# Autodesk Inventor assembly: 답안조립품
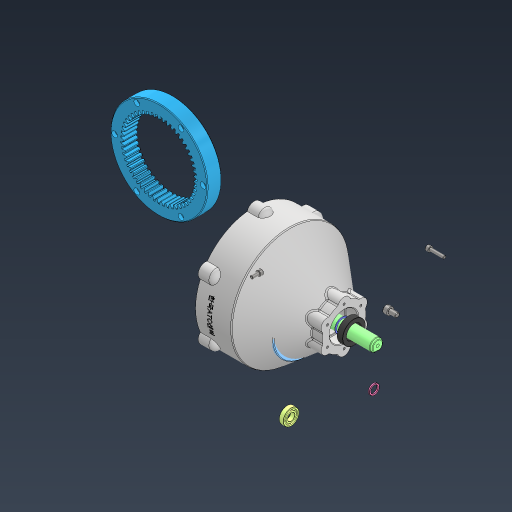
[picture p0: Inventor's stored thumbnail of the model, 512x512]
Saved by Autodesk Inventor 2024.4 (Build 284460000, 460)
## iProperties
Created: 2026-05
Part Number: 답안조립품
Document SubType Name: Assembly
Designer: user
Author: user
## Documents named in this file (19)
- C:\Users\user\Desktop\760503V1002\답안조립품.iam
- C:\Users\user\Desktop\750803V1006\6각 너트 M14x1\6각 구멍붙이 볼트 M4x10\6각 구멍붙이 볼트 M4x10.ipt
- C:\Users\user\Desktop\750803V1006\6각 너트 M14x1\6각 구멍붙이 볼트 M4x20\6각 구멍붙이 볼트 M4x20.ipt
- C:\Users\user\Desktop\750803V1006\6각 너트 M14x1\6각 구멍붙이 볼트 M6x10\6각 구멍붙이 볼트 M6x10.ipt
- C:\Users\user\Desktop\750803V1006\6각 너트 M14x1\깊은 홈 볼 베어링 6010\깊은 홈 볼 베어링 6010.ipt
- C:\Users\user\Desktop\750803V1006\6각 너트 M14x1\깊은 홈 볼 베어링 6203\깊은 홈 볼 베어링 6203.ipt
- C:\Users\user\Desktop\750803V1006\6각 너트 M14x1\깊은 홈 볼 베어링 6900\깊은 홈 볼 베어링 6900.ipt
- C:\Users\user\Desktop\750803V1006\6각 너트 M14x1\링 기어\링 기어.ipt
- C:\Users\user\Desktop\750803V1006\6각 너트 M14x1\선 기어 축\선 기어 축.ipt
- C:\Users\user\Desktop\750803V1006\6각 너트 M14x1\엔드 캡\엔드 캡.ipt
- C:\Users\user\Desktop\750803V1006\6각 너트 M14x1\오일 실 17 32 8\오일 실 17 32 8.ipt
- C:\Users\user\Desktop\750803V1006\6각 너트 M14x1\유성 기어\유성 기어.ipt
- C:\Users\user\Desktop\750803V1006\6각 너트 M14x1\유성 축\유성 축.ipt
- C:\Users\user\Desktop\750803V1006\6각 너트 M14x1\유성 캐리어 커버\유성 캐리어 커버.ipt
- C:\Users\user\Desktop\750803V1006\6각 너트 M14x1\유성 캐리어\유성 캐리어.ipt
- C:\Users\user\Desktop\750803V1006\6각 너트 M14x1\축용 C형 멈춤링 17\축용 C형 멈춤링 17.ipt
- C:\Users\user\Desktop\750803V1006\6각 너트 M14x1\칼라\칼라.ipt
- C:\Users\user\Desktop\750803V1006\6각 너트 M14x1\커버\커버.ipt
- C:\Users\user\Desktop\760503V1002\본체.ipt
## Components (6 placed, 3 different names)
1. 6각 구멍붙이 볼트 M4x20:1
2. 6각 구멍붙이 볼트 M6x10:1
3. 6각 구멍붙이 볼트 M4x10:2
4. 6각 구멍붙이 볼트 M4x10:4
5. 6각 구멍붙이 볼트 M4x10:5
6. 6각 구멍붙이 볼트 M4x10:6
